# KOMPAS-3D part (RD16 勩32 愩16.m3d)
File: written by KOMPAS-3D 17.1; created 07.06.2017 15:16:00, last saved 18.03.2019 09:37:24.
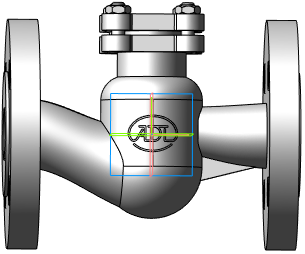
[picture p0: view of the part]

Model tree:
1. Операция без истории:2  (labels: Сталь 20  ГОСТ 1050-88)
